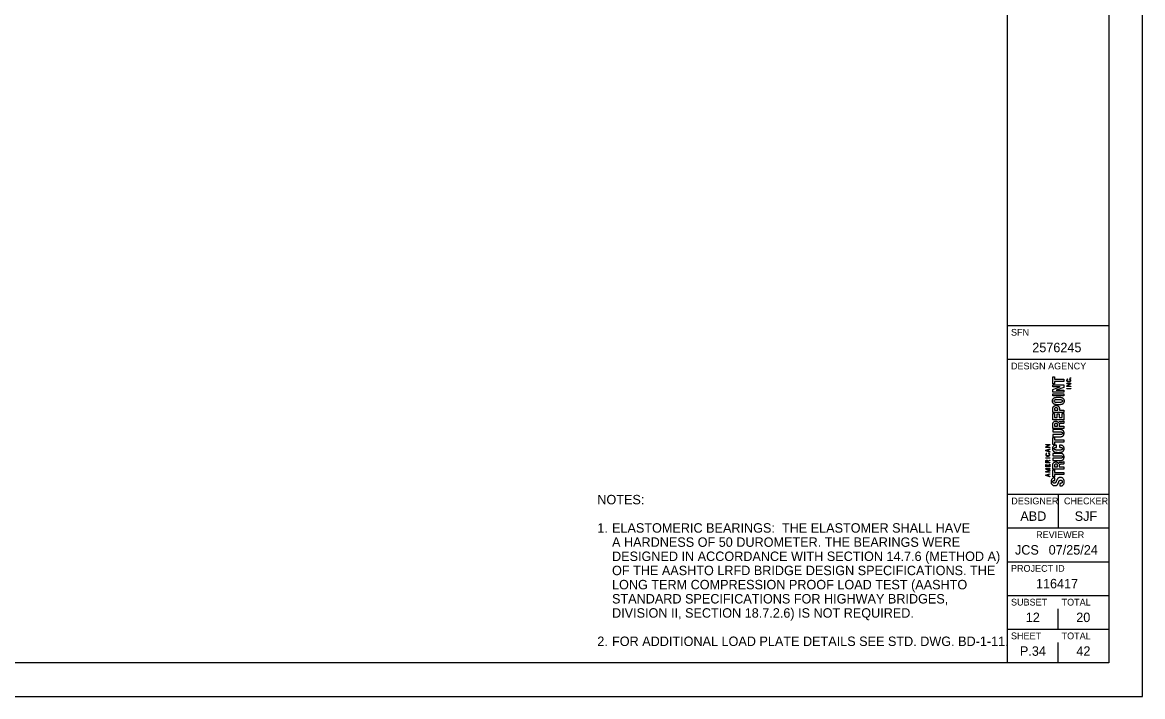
# Model space of a CAD drawing. Extents: x 0 to 34, y 0 to 22.
# Drawn here: x 17.4 to 34, y 0 to 9.99 of the extents above; entities that cross this region are included whole.
import ezdxf

# ---------------------------------------------------------------- set-up
doc = ezdxf.new("R2010")
doc.units = 0
for name, color, linetype in [('BR_P_Gen_Text', 7, 'Continuous'), ('SH_Border', 7, 'Continuous'), ('SH_Cut_Line', 7, 'Continuous'), ('SH_Data', 7, 'Continuous')]:
    doc.layers.add(name, color=color, linetype=linetype)

msp = doc.modelspace()

# ---------------------------------------------------------------- linework, layer by layer
at = {"layer": 'SH_Border'}
for p, q in [((32, 0.5), (32, 21.5)), ((32, 5.5), (33.5, 5.5)), ((32, 5), (33.5, 5)), ((32, 3), (33.5, 3)), ((32.75, 3), (32.75, 2.5)), ((32, 2.5), (33.5, 2.5)), ((32, 2), (33.5, 2)), ((32, 1.5), (33.5, 1.5)), ((32, 1), (33.5, 1))]:
    msp.add_line(p, q, dxfattribs=at)
msp.add_lwpolyline([(1.5, 21.5), (33.5, 21.5), (33.5, 0.5), (1.5, 0.5)], close=True, dxfattribs=at)
at = {"layer": 'SH_Cut_Line'}
msp.add_lwpolyline([(0, 0), (34, 0), (34, 22), (0, 22)], close=True, dxfattribs=at)
at = {"layer": 'SH_Data'}
for p, q in [((32.75, 4), (32.75, 4)), ((32.75, 4), (32.75, 4)), ((32.75, 1), (32.75, 1.3)), ((32.375, 0.675), (32.375, 0.675)), ((32.75, 0.5), (32.75, 0.8))]:
    msp.add_line(p, q, dxfattribs=at)
for points in [[(32.67, 4.739), (32.697, 4.739), (32.697, 4.704), (32.833, 4.704), (32.833, 4.671), (32.697, 4.671), (32.697, 4.635), (32.67, 4.635), (32.67, 4.739)], [(32.935, 4.718), (32.927, 4.718), (32.927, 4.725), (32.935, 4.725), (32.935, 4.718)], [(32.67, 4.551), (32.781, 4.591), (32.781, 4.592), (32.67, 4.592), (32.67, 4.622), (32.833, 4.622), (32.833, 4.584), (32.719, 4.544), (32.719, 4.544), (32.833, 4.544), (32.833, 4.513), (32.67, 4.513), (32.67, 4.551)], [(32.833, 4.457), (32.67, 4.457), (32.67, 4.49), (32.833, 4.49), (32.833, 4.457)], [(32.875, 4.596), (32.875, 4.605), (32.925, 4.634), (32.925, 4.634), (32.875, 4.634), (32.875, 4.639), (32.935, 4.639), (32.935, 4.634), (32.88, 4.602), (32.88, 4.601), (32.935, 4.601), (32.935, 4.596), (32.875, 4.596)], [(32.875, 4.561), (32.875, 4.567), (32.935, 4.567), (32.935, 4.561), (32.875, 4.561)], [(32.833, 4.212), (32.67, 4.212), (32.67, 4.269)], [(32.67, 4.194), (32.697, 4.194), (32.697, 4.135), (32.735, 4.135), (32.735, 4.19), (32.762, 4.19), (32.762, 4.135), (32.806, 4.135), (32.806, 4.196), (32.833, 4.196), (32.833, 4.103), (32.67, 4.103), (32.67, 4.194)], [(32.694, 4.244), (32.743, 4.244), (32.743, 4.259)], [(32.694, 4.258), (32.694, 4.244)], [(32.768, 4.262), (32.768, 4.244), (32.833, 4.244), (32.833, 4.212)], [(32.833, 3.976), (32.67, 3.976), (32.67, 4.037)], [(32.694, 4.025), (32.694, 4.009)], [(32.694, 4.009), (32.741, 4.009), (32.741, 4.023)], [(32.752, 4.054), (32.752, 4.054)], [(32.764, 4.027), (32.764, 4.009), (32.833, 4.009), (32.833, 3.976)], [(32.816, 4.048), (32.784, 4.047)], [(32.832, 4.087), (32.833, 4.087), (32.833, 4.052)], [(32.67, 3.841), (32.697, 3.841), (32.697, 3.805), (32.833, 3.805), (32.833, 3.773), (32.697, 3.773), (32.697, 3.737), (32.67, 3.737), (32.67, 3.841)], [(32.565, 3.694), (32.565, 3.703), (32.615, 3.731), (32.615, 3.731), (32.565, 3.731), (32.565, 3.737), (32.625, 3.737), (32.625, 3.731), (32.569, 3.699), (32.569, 3.699), (32.625, 3.699), (32.625, 3.694), (32.565, 3.694)], [(32.625, 3.625), (32.565, 3.644), (32.565, 3.652), (32.625, 3.671), (32.625, 3.665), (32.605, 3.659), (32.605, 3.637), (32.625, 3.631), (32.625, 3.625)], [(32.601, 3.638), (32.601, 3.658), (32.569, 3.648), (32.569, 3.648), (32.601, 3.638)], [(32.565, 3.534), (32.565, 3.539), (32.625, 3.539), (32.625, 3.534), (32.565, 3.534)], [(32.596, 3.492), (32.625, 3.506), (32.625, 3.5), (32.597, 3.487), (32.597, 3.471), (32.625, 3.471), (32.625, 3.466), (32.565, 3.466), (32.565, 3.486)], [(32.625, 3.407), (32.565, 3.407), (32.565, 3.441), (32.569, 3.441), (32.569, 3.413), (32.591, 3.413), (32.591, 3.433), (32.596, 3.433), (32.596, 3.413), (32.62, 3.413), (32.62, 3.443), (32.625, 3.443), (32.625, 3.407)], [(32.625, 3.326), (32.565, 3.326), (32.565, 3.336), (32.615, 3.352), (32.615, 3.353), (32.565, 3.369), (32.565, 3.379), (32.625, 3.379), (32.625, 3.373), (32.569, 3.373), (32.569, 3.373), (32.625, 3.355), (32.625, 3.35), (32.569, 3.332), (32.569, 3.332), (32.625, 3.332), (32.625, 3.326)], [(32.569, 3.471), (32.593, 3.471), (32.593, 3.486)], [(32.569, 3.486), (32.569, 3.471)], [(32.833, 3.373), (32.67, 3.373), (32.67, 3.434)], [(32.67, 3.36), (32.697, 3.36), (32.697, 3.324), (32.833, 3.324), (32.833, 3.291), (32.697, 3.291), (32.697, 3.256), (32.67, 3.256), (32.67, 3.36)], [(32.694, 3.422), (32.694, 3.406)], [(32.694, 3.406), (32.741, 3.406), (32.741, 3.42)], [(32.752, 3.451), (32.752, 3.451)], [(32.764, 3.424), (32.764, 3.406), (32.833, 3.406), (32.833, 3.373)], [(32.816, 3.444), (32.784, 3.444)], [(32.832, 3.484), (32.833, 3.484), (32.833, 3.449)], [(32.625, 3.258), (32.565, 3.277), (32.565, 3.285), (32.625, 3.304), (32.625, 3.298), (32.605, 3.292), (32.605, 3.269), (32.625, 3.263), (32.625, 3.258)], [(32.601, 3.271), (32.601, 3.291), (32.569, 3.281), (32.569, 3.281), (32.601, 3.271)]]:
    msp.add_lwpolyline(points, dxfattribs=at)
for points in [[(32.893, 4.701), (32.889, 4.699), (32.885, 4.697), (32.883, 4.695), (32.88, 4.693), (32.879, 4.69), (32.879, 4.686), (32.879, 4.683), (32.88, 4.681), (32.881, 4.678), (32.882, 4.676), (32.884, 4.675), (32.887, 4.673), (32.889, 4.672), (32.892, 4.671), (32.895, 4.67), (32.898, 4.669), (32.902, 4.669), (32.905, 4.669), (32.909, 4.669), (32.912, 4.669), (32.915, 4.67), (32.919, 4.671), (32.921, 4.672), (32.924, 4.673), (32.926, 4.675), (32.928, 4.676), (32.929, 4.679), (32.931, 4.681), (32.931, 4.684), (32.931, 4.687), (32.931, 4.689), (32.931, 4.691), (32.93, 4.693), (32.929, 4.694), (32.928, 4.696), (32.927, 4.697), (32.926, 4.698), (32.924, 4.699), (32.922, 4.7), (32.921, 4.7), (32.919, 4.701), (32.917, 4.702), (32.917, 4.702), (32.918, 4.707), (32.918, 4.707), (32.92, 4.706), (32.923, 4.705), (32.925, 4.704), (32.927, 4.703), (32.929, 4.702), (32.931, 4.7), (32.932, 4.699), (32.934, 4.697), (32.934, 4.695), (32.935, 4.692), (32.936, 4.69), (32.936, 4.687), (32.936, 4.683), (32.935, 4.68), (32.934, 4.677), (32.932, 4.674), (32.93, 4.672), (32.927, 4.67), (32.925, 4.668), (32.921, 4.666), (32.918, 4.665), (32.914, 4.664), (32.91, 4.664), (32.905, 4.664), (32.901, 4.664), (32.896, 4.664), (32.893, 4.665), (32.889, 4.666), (32.886, 4.668), (32.883, 4.67), (32.88, 4.672), (32.878, 4.674), (32.877, 4.677), (32.875, 4.68), (32.875, 4.683), (32.875, 4.687), (32.875, 4.689), (32.875, 4.692), (32.876, 4.694), (32.877, 4.696), (32.878, 4.698), (32.88, 4.699), (32.881, 4.701), (32.883, 4.702), (32.885, 4.703), (32.887, 4.704), (32.889, 4.705), (32.892, 4.706), (32.892, 4.706), (32.893, 4.701), (32.893, 4.701)], [(32.751, 4.326), (32.739, 4.326), (32.727, 4.326), (32.717, 4.328), (32.706, 4.329), (32.697, 4.331), (32.69, 4.335), (32.682, 4.339), (32.677, 4.345), (32.672, 4.352), (32.668, 4.359), (32.666, 4.369), (32.666, 4.382), (32.666, 4.394), (32.668, 4.404), (32.672, 4.411), (32.677, 4.418), (32.682, 4.424), (32.69, 4.428), (32.697, 4.432), (32.706, 4.434), (32.717, 4.436), (32.727, 4.437), (32.739, 4.437), (32.751, 4.437), (32.758, 4.437), (32.764, 4.437), (32.771, 4.437)], [(32.751, 4.359), (32.762, 4.359), (32.771, 4.359), (32.779, 4.359), (32.787, 4.36), (32.793, 4.361), (32.798, 4.363), (32.803, 4.364), (32.806, 4.367), (32.808, 4.37), (32.81, 4.373), (32.812, 4.377), (32.812, 4.382), (32.812, 4.386), (32.81, 4.39), (32.808, 4.393), (32.806, 4.396), (32.803, 4.399), (32.798, 4.4), (32.793, 4.402), (32.787, 4.403), (32.779, 4.404), (32.771, 4.404), (32.762, 4.404), (32.751, 4.404), (32.74, 4.404), (32.731, 4.404), (32.723, 4.404), (32.716, 4.403), (32.709, 4.402), (32.704, 4.4), (32.7, 4.399), (32.696, 4.396), (32.694, 4.393), (32.692, 4.39), (32.691, 4.386), (32.691, 4.382), (32.691, 4.377), (32.692, 4.373), (32.694, 4.37), (32.696, 4.367), (32.7, 4.364), (32.704, 4.363), (32.709, 4.361), (32.716, 4.36), (32.723, 4.359), (32.731, 4.359), (32.74, 4.359), (32.751, 4.359)], [(32.771, 4.437), (32.776, 4.436), (32.781, 4.436), (32.785, 4.436), (32.796, 4.434), (32.805, 4.432), (32.812, 4.428), (32.82, 4.424), (32.825, 4.418), (32.83, 4.411), (32.834, 4.404), (32.836, 4.394), (32.836, 4.382), (32.836, 4.369), (32.834, 4.359), (32.83, 4.352), (32.825, 4.345), (32.82, 4.339), (32.812, 4.335), (32.805, 4.331), (32.796, 4.329), (32.785, 4.328), (32.775, 4.326), (32.763, 4.326), (32.751, 4.326)], [(32.67, 4.269), (32.67, 4.277), (32.671, 4.284), (32.674, 4.29), (32.677, 4.296), (32.68, 4.3), (32.685, 4.304), (32.689, 4.307), (32.695, 4.31), (32.701, 4.312), (32.706, 4.313), (32.712, 4.314), (32.719, 4.314), (32.727, 4.314), (32.734, 4.313), (32.741, 4.31), (32.747, 4.308), (32.752, 4.304), (32.756, 4.3), (32.76, 4.295), (32.763, 4.29), (32.765, 4.283), (32.767, 4.277), (32.768, 4.27), (32.768, 4.262)], [(32.743, 4.259), (32.743, 4.266), (32.741, 4.271), (32.737, 4.275), (32.733, 4.279), (32.727, 4.281), (32.719, 4.281), (32.711, 4.281), (32.705, 4.279), (32.7, 4.276), (32.696, 4.272), (32.694, 4.266), (32.694, 4.258)], [(32.67, 4.037), (32.67, 4.051), (32.673, 4.062), (32.68, 4.069), (32.687, 4.077), (32.698, 4.081), (32.712, 4.081), (32.723, 4.081), (32.732, 4.079), (32.739, 4.074), (32.745, 4.07), (32.75, 4.063), (32.752, 4.054)], [(32.741, 4.023), (32.741, 4.031), (32.739, 4.037), (32.735, 4.042), (32.732, 4.046), (32.725, 4.048), (32.717, 4.048), (32.702, 4.048), (32.694, 4.04), (32.694, 4.025)], [(32.752, 4.054), (32.753, 4.059), (32.755, 4.064), (32.757, 4.067), (32.759, 4.071), (32.762, 4.073), (32.766, 4.075), (32.769, 4.077), (32.774, 4.078), (32.78, 4.079), (32.786, 4.08), (32.794, 4.08), (32.802, 4.08), (32.811, 4.08), (32.818, 4.081), (32.822, 4.082), (32.827, 4.082), (32.83, 4.084), (32.832, 4.087)], [(32.784, 4.047), (32.778, 4.046), (32.773, 4.045), (32.769, 4.042), (32.766, 4.039), (32.764, 4.034), (32.764, 4.027)], [(32.833, 4.052), (32.831, 4.05), (32.828, 4.049), (32.825, 4.049), (32.822, 4.048), (32.819, 4.048), (32.816, 4.048)], [(32.67, 3.885), (32.67, 3.885), (32.783, 3.885), (32.783, 3.885), (32.787, 3.885), (32.791, 3.885), (32.795, 3.886), (32.798, 3.887), (32.801, 3.888), (32.803, 3.889), (32.806, 3.89), (32.808, 3.892), (32.809, 3.895), (32.811, 3.897), (32.812, 3.901), (32.812, 3.904), (32.812, 3.908), (32.811, 3.911), (32.809, 3.914), (32.808, 3.917), (32.806, 3.918), (32.803, 3.92), (32.801, 3.921), (32.798, 3.922), (32.795, 3.923), (32.791, 3.923), (32.787, 3.924), (32.783, 3.924), (32.783, 3.924), (32.67, 3.924), (32.67, 3.924), (32.67, 3.924), (32.67, 3.957), (32.67, 3.957), (32.67, 3.957), (32.783, 3.957), (32.783, 3.957), (32.794, 3.957), (32.802, 3.955), (32.809, 3.952), (32.816, 3.949), (32.821, 3.945), (32.825, 3.941), (32.829, 3.936), (32.832, 3.93), (32.834, 3.924), (32.835, 3.918), (32.836, 3.911), (32.836, 3.904), (32.836, 3.898), (32.835, 3.891), (32.834, 3.885), (32.833, 3.879), (32.83, 3.873), (32.826, 3.868), (32.822, 3.863), (32.817, 3.86), (32.81, 3.857), (32.803, 3.854), (32.794, 3.852), (32.783, 3.852), (32.783, 3.852), (32.67, 3.852), (32.67, 3.852), (32.67, 3.852), (32.67, 3.885), (32.67, 3.885)], [(32.725, 3.693), (32.713, 3.693), (32.704, 3.692), (32.699, 3.689), (32.693, 3.686), (32.691, 3.681), (32.691, 3.674), (32.691, 3.67), (32.692, 3.666), (32.694, 3.663), (32.696, 3.661), (32.7, 3.659), (32.705, 3.657), (32.71, 3.656), (32.716, 3.655), (32.724, 3.654), (32.732, 3.653), (32.742, 3.653), (32.753, 3.653), (32.766, 3.653), (32.776, 3.653), (32.783, 3.654), (32.791, 3.655), (32.797, 3.656), (32.801, 3.658), (32.805, 3.66), (32.808, 3.662), (32.809, 3.665), (32.811, 3.668), (32.812, 3.671), (32.812, 3.674), (32.812, 3.677), (32.811, 3.68), (32.81, 3.682), (32.809, 3.685), (32.807, 3.687), (32.804, 3.689), (32.801, 3.691), (32.797, 3.692), (32.792, 3.693), (32.786, 3.694), (32.779, 3.695), (32.77, 3.695), (32.77, 3.695), (32.77, 3.728), (32.77, 3.728), (32.779, 3.728), (32.787, 3.727), (32.795, 3.726), (32.803, 3.724), (32.81, 3.722), (32.816, 3.718), (32.822, 3.714), (32.827, 3.709), (32.831, 3.702), (32.834, 3.696), (32.836, 3.687), (32.836, 3.676), (32.836, 3.663), (32.834, 3.654), (32.83, 3.646), (32.825, 3.639), (32.82, 3.633), (32.812, 3.629), (32.805, 3.626), (32.796, 3.623), (32.785, 3.622), (32.775, 3.621), (32.763, 3.62), (32.751, 3.62), (32.739, 3.62), (32.727, 3.621), (32.717, 3.622), (32.706, 3.623), (32.697, 3.626), (32.69, 3.629), (32.682, 3.633), (32.677, 3.639), (32.672, 3.646), (32.668, 3.654), (32.666, 3.663), (32.666, 3.676), (32.666, 3.688), (32.668, 3.697), (32.672, 3.704), (32.676, 3.71), (32.681, 3.715), (32.687, 3.719), (32.692, 3.722), (32.699, 3.724), (32.706, 3.725), (32.712, 3.726), (32.719, 3.726), (32.725, 3.726), (32.725, 3.726), (32.725, 3.693), (32.725, 3.693)], [(32.582, 3.601), (32.578, 3.6), (32.575, 3.598), (32.572, 3.595), (32.57, 3.593), (32.569, 3.59), (32.569, 3.586), (32.569, 3.583), (32.569, 3.581), (32.571, 3.579), (32.572, 3.577), (32.574, 3.575), (32.576, 3.574), (32.579, 3.572), (32.581, 3.571), (32.585, 3.57), (32.588, 3.57), (32.591, 3.569), (32.595, 3.569), (32.598, 3.569), (32.602, 3.57), (32.605, 3.57), (32.608, 3.571), (32.611, 3.572), (32.613, 3.574), (32.616, 3.575), (32.618, 3.577), (32.619, 3.579), (32.62, 3.581), (32.621, 3.584), (32.621, 3.587), (32.621, 3.589), (32.62, 3.591), (32.62, 3.593), (32.619, 3.595), (32.618, 3.596), (32.617, 3.597), (32.615, 3.598), (32.614, 3.599), (32.612, 3.6), (32.61, 3.601), (32.608, 3.602), (32.606, 3.602), (32.606, 3.602), (32.607, 3.607), (32.607, 3.607), (32.61, 3.607), (32.612, 3.606), (32.615, 3.605), (32.617, 3.604), (32.619, 3.602), (32.62, 3.601), (32.622, 3.599), (32.623, 3.597), (32.624, 3.595), (32.625, 3.593), (32.625, 3.59), (32.625, 3.587), (32.625, 3.583), (32.625, 3.58), (32.623, 3.577), (32.622, 3.574), (32.62, 3.572), (32.617, 3.57), (32.614, 3.568), (32.611, 3.567), (32.607, 3.566), (32.604, 3.565), (32.599, 3.564), (32.595, 3.564), (32.59, 3.564), (32.586, 3.565), (32.582, 3.566), (32.579, 3.567), (32.575, 3.568), (32.573, 3.57), (32.57, 3.572), (32.568, 3.574), (32.566, 3.577), (32.565, 3.58), (32.564, 3.583), (32.564, 3.587), (32.564, 3.59), (32.565, 3.592), (32.566, 3.594), (32.566, 3.596), (32.568, 3.598), (32.569, 3.599), (32.571, 3.601), (32.572, 3.602), (32.575, 3.603), (32.577, 3.604), (32.579, 3.605), (32.581, 3.606), (32.581, 3.606), (32.582, 3.601), (32.582, 3.601)], [(32.565, 3.486), (32.565, 3.492), (32.566, 3.496), (32.569, 3.499), (32.572, 3.503), (32.576, 3.504), (32.581, 3.504), (32.585, 3.504), (32.588, 3.503), (32.591, 3.501), (32.593, 3.499), (32.595, 3.496), (32.596, 3.492)], [(32.593, 3.486), (32.593, 3.49), (32.592, 3.493), (32.59, 3.495), (32.588, 3.497), (32.585, 3.499), (32.581, 3.499), (32.577, 3.499), (32.575, 3.498), (32.573, 3.495), (32.57, 3.493), (32.569, 3.49), (32.569, 3.486)], [(32.67, 3.532), (32.67, 3.532), (32.783, 3.532), (32.783, 3.532), (32.787, 3.532), (32.791, 3.533), (32.795, 3.533), (32.798, 3.534), (32.801, 3.535), (32.803, 3.536), (32.806, 3.538), (32.808, 3.54), (32.809, 3.542), (32.811, 3.545), (32.812, 3.548), (32.812, 3.552), (32.812, 3.556), (32.811, 3.559), (32.809, 3.561), (32.808, 3.564), (32.806, 3.566), (32.803, 3.567), (32.801, 3.569), (32.798, 3.57), (32.795, 3.57), (32.791, 3.571), (32.787, 3.571), (32.783, 3.571), (32.783, 3.571), (32.67, 3.571), (32.67, 3.571), (32.67, 3.571), (32.67, 3.604), (32.67, 3.604), (32.67, 3.604), (32.783, 3.604), (32.783, 3.604), (32.794, 3.604), (32.802, 3.602), (32.809, 3.6), (32.816, 3.597), (32.821, 3.593), (32.825, 3.588), (32.829, 3.583), (32.832, 3.577), (32.834, 3.571), (32.835, 3.565), (32.836, 3.558), (32.836, 3.552), (32.836, 3.545), (32.835, 3.539), (32.834, 3.532), (32.833, 3.526), (32.83, 3.521), (32.826, 3.516), (32.822, 3.511), (32.817, 3.507), (32.81, 3.504), (32.803, 3.501), (32.794, 3.5), (32.783, 3.5), (32.783, 3.5), (32.67, 3.5), (32.67, 3.5), (32.67, 3.5), (32.67, 3.532), (32.67, 3.532)], [(32.67, 3.434), (32.67, 3.448), (32.673, 3.458), (32.68, 3.466), (32.687, 3.474), (32.698, 3.478), (32.712, 3.478), (32.723, 3.478), (32.732, 3.475), (32.739, 3.471), (32.745, 3.467), (32.75, 3.46), (32.752, 3.451)], [(32.741, 3.42), (32.741, 3.428), (32.739, 3.434), (32.735, 3.438), (32.732, 3.443), (32.725, 3.445), (32.717, 3.445), (32.702, 3.445), (32.694, 3.437), (32.694, 3.422)], [(32.752, 3.451), (32.753, 3.456), (32.755, 3.461), (32.757, 3.464), (32.759, 3.467), (32.762, 3.47), (32.766, 3.472), (32.769, 3.474), (32.774, 3.475), (32.78, 3.476), (32.786, 3.476), (32.794, 3.477), (32.802, 3.477), (32.811, 3.477), (32.818, 3.478), (32.822, 3.478), (32.827, 3.479), (32.83, 3.481), (32.832, 3.484)], [(32.784, 3.444), (32.778, 3.443), (32.773, 3.442), (32.769, 3.439), (32.766, 3.436), (32.764, 3.431), (32.764, 3.424)], [(32.833, 3.449), (32.831, 3.447), (32.828, 3.446), (32.825, 3.445), (32.822, 3.445), (32.819, 3.445), (32.816, 3.444)], [(32.775, 3.161), (32.775, 3.161), (32.781, 3.161), (32.781, 3.161), (32.785, 3.161), (32.789, 3.162), (32.793, 3.162), (32.796, 3.163), (32.799, 3.164), (32.801, 3.166), (32.804, 3.168), (32.806, 3.171), (32.807, 3.174), (32.809, 3.177), (32.809, 3.181), (32.809, 3.186), (32.809, 3.192), (32.807, 3.197), (32.804, 3.201), (32.8, 3.206), (32.794, 3.208), (32.786, 3.208), (32.782, 3.208), (32.779, 3.208), (32.776, 3.207), (32.773, 3.205), (32.77, 3.204), (32.767, 3.201), (32.765, 3.198), (32.763, 3.195), (32.761, 3.191), (32.759, 3.187), (32.757, 3.181), (32.755, 3.175), (32.752, 3.167), (32.749, 3.16), (32.745, 3.154), (32.742, 3.147), (32.738, 3.142), (32.734, 3.138), (32.73, 3.134), (32.725, 3.131), (32.719, 3.129), (32.713, 3.128), (32.706, 3.127), (32.699, 3.127), (32.68, 3.127), (32.667, 3.132), (32.658, 3.142), (32.649, 3.152), (32.644, 3.166), (32.644, 3.184), (32.644, 3.192), (32.645, 3.2), (32.647, 3.207), (32.649, 3.214), (32.651, 3.22), (32.656, 3.225), (32.66, 3.23), (32.665, 3.234), (32.671, 3.237), (32.677, 3.24), (32.685, 3.241), (32.694, 3.241), (32.694, 3.241), (32.699, 3.241), (32.699, 3.241), (32.699, 3.241), (32.699, 3.205), (32.699, 3.205), (32.69, 3.205), (32.683, 3.204), (32.679, 3.201), (32.674, 3.197), (32.671, 3.192), (32.671, 3.185), (32.671, 3.181), (32.672, 3.178), (32.673, 3.175), (32.675, 3.172), (32.676, 3.17), (32.678, 3.168), (32.68, 3.167), (32.682, 3.165), (32.685, 3.165), (32.688, 3.164), (32.69, 3.164), (32.693, 3.164), (32.699, 3.164), (32.704, 3.165), (32.707, 3.168), (32.711, 3.17), (32.715, 3.175), (32.718, 3.183), (32.718, 3.183), (32.731, 3.212), (32.731, 3.212), (32.734, 3.219), (32.737, 3.225), (32.74, 3.229), (32.744, 3.234), (32.747, 3.237), (32.751, 3.24), (32.755, 3.243), (32.76, 3.245), (32.764, 3.246), (32.769, 3.247), (32.774, 3.247), (32.78, 3.247), (32.799, 3.247), (32.814, 3.242), (32.823, 3.23), (32.832, 3.219), (32.837, 3.203), (32.837, 3.183), (32.837, 3.162), (32.832, 3.147), (32.823, 3.138), (32.813, 3.128), (32.8, 3.124), (32.783, 3.124), (32.783, 3.124), (32.775, 3.124), (32.775, 3.124), (32.775, 3.124), (32.775, 3.161), (32.775, 3.161)]]:
    msp.add_open_spline(points, degree=3, dxfattribs=at)

# ---------------------------------------------------------------- texts
at = {"layer": 'BR_P_Gen_Text'}
for s, p in [('NOTES:', (25.92, 2.85)), ('1.', (25.92, 2.43)), ('ELASTOMERIC BEARINGS:  THE ELASTOMER SHALL HAVE ', (26.138, 2.43)), ('A HARDNESS OF 50 DUROMETER. THE BEARINGS WERE ', (26.138, 2.22)), ('DESIGNED IN ACCORDANCE WITH SECTION 14.7.6 (METHOD A)', (26.138, 2.01)), ('OF THE AASHTO LRFD BRIDGE DESIGN SPECIFICATIONS. THE', (26.138, 1.8)), ('LONG TERM COMPRESSION PROOF LOAD TEST (AASHTO', (26.138, 1.59)), ('STANDARD SPECIFICATIONS FOR HIGHWAY BRIDGES,', (26.138, 1.38)), ('DIVISION II, SECTION 18.7.2.6) IS NOT REQUIRED.', (26.138, 1.17)), ('2.', (25.92, 0.75)), ('FOR ADDITIONAL LOAD PLATE DETAILS SEE STD. DWG. BD-1-11.', (26.138, 0.75))]:
    msp.add_text(s, height=0.14, dxfattribs=at).set_placement(p)
at = {"layer": 'SH_Data'}
for s, height, p in [('SFN', 0.1, (32.05, 5.35)), ('2576245', 0.14, (32.365, 5.105)), ('DESIGN AGENCY', 0.1, (32.05, 4.85)), ('DESIGNER', 0.1, (32.054, 2.85)), ('CHECKER', 0.1, (32.835, 2.85)), ('ABD', 0.14, (32.188, 2.605)), ('SJF', 0.14, (32.994, 2.605)), ('REVIEWER', 0.1, (32.422, 2.35)), ('JCS', 0.14, (32.109, 2.105)), ('07/25/24', 0.14, (32.608, 2.105)), ('PROJECT ID', 0.1, (32.05, 1.85)), ('116417', 0.14, (32.42, 1.605)), ('SUBSET', 0.1, (32.05, 1.35)), ('TOTAL', 0.1, (32.8, 1.35)), ('12', 0.14, (32.269, 1.105)), ('20', 0.14, (33.017, 1.105)), ('SHEET', 0.1, (32.05, 0.85)), ('TOTAL', 0.1, (32.8, 0.85)), ('P.34', 0.14, (32.182, 0.605)), ('42', 0.14, (33.019, 0.605))]:
    msp.add_text(s, height=height, dxfattribs=at).set_placement(p)

doc.saveas('drawing.dxf')
